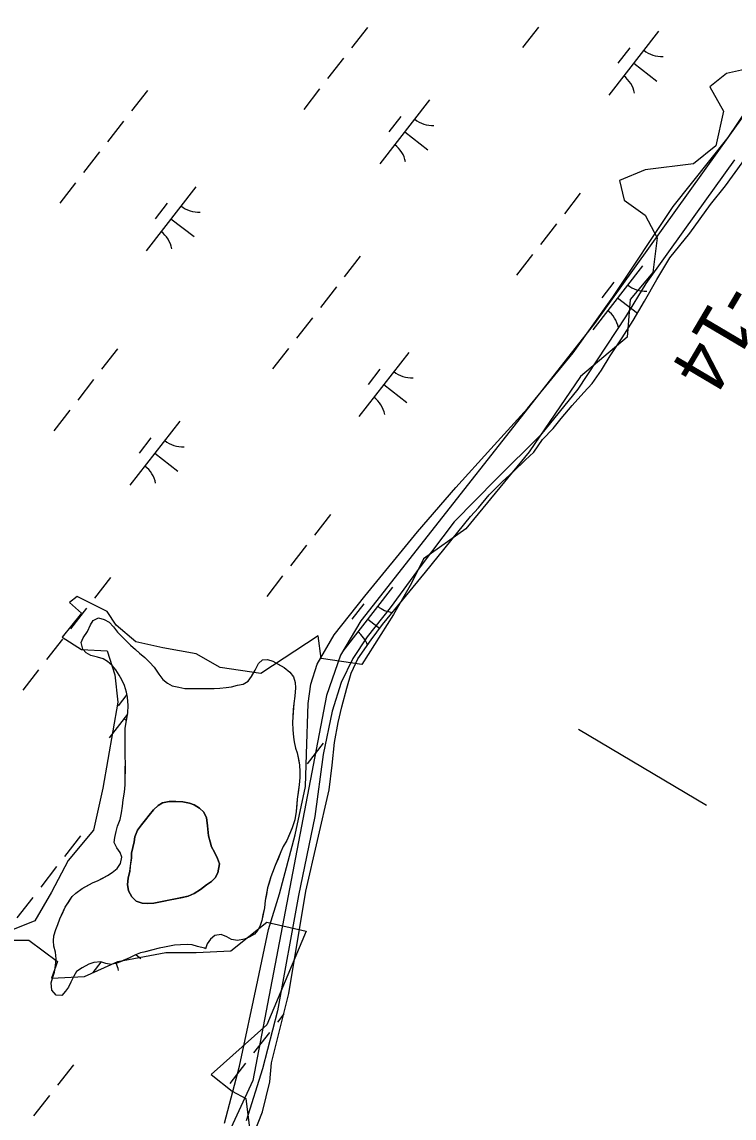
# Model space of a CAD drawing. Extents: x 3888273 to 3909528, y 158682 to 181032.
# Drawn here: x 3897016 to 3897455, y 166620 to 167296 of the extents above; entities that cross this region are included whole.
import ezdxf

# ---------------------------------------------------------------- set-up
doc = ezdxf.new("R2010")
doc.units = 0
for name, color, linetype in [('V-LEVE-TOET', 7, 'Continuous'), ('V-RIVR-EDGE', 7, 'Continuous'), ('V-RIVR-JETY', 7, 'Continuous'), ('V-RIVR-RANG', 7, 'Continuous'), ('V-RRAP-FSHR', 7, 'Continuous'), ('V-TOPO-SHOR', 7, 'Continuous'), ('V-WETL-SWMP', 7, 'Continuous')]:
    doc.layers.add(name, color=color, linetype=linetype)

msp = doc.modelspace()

# ---------------------------------------------------------------- linework, layer by layer
at = {"layer": 'V-LEVE-TOET'}
msp.add_line((3897359.17, 166859.83), (3897438.06, 166813.05), dxfattribs=at)
at = {"layer": 'V-RIVR-EDGE'}
for points in [[(3897463.44, 167266.8), (3897450.43, 167264.01), (3897440.21, 167255.65), (3897448.57, 167240.78), (3897443.93, 167219.41), (3897429.99, 167208.26), (3897400.25, 167204.54), (3897384.46, 167198.04), (3897387.25, 167185.96), (3897400.25, 167176.67), (3897407.69, 167162.73), (3897404.9, 167141.36), (3897390.96, 167124.63), (3897389.1, 167101.4), (3897360.3, 167077.24), (3897328.71, 167030.78), (3897289.68, 166983.39), (3897263.66, 166964.81), (3897256.23, 166949.94), (3897245.08, 166930.43), (3897225.56, 166899.76), (3897200.47, 166903.48), (3897198.62, 166917.42), (3897163.31, 166894.19), (3897138.22, 166897.9), (3897123.35, 166906.27), (3897102.91, 166909.98), (3897086.18, 166913.7), (3897074.1, 166923.92), (3897068.53, 166932.28), (3897049.94, 166941.58), (3897045.3, 166937.86), (3897052.73, 166931.35), (3897040.65, 166916.49), (3897052.73, 166909.05), (3897068.53, 166908.12), (3897073.17, 166893.26), (3897075.03, 166876.53), (3897065.74, 166823.57), (3897060.16, 166797.55), (3897044.37, 166778.96), (3897034.15, 166759.45), (3897023.92, 166741.8), (3896991.4, 166728.79)], [(3897006.27, 166729.72), (3897020.21, 166729.72), (3897037.86, 166716.71), (3897034.15, 166706.49), (3897054.59, 166707.41), (3897075.03, 166716.71), (3897104.77, 166722.28), (3897123.35, 166722.28), (3897144.72, 166723.21), (3897167.02, 166740.87), (3897191.18, 166735.29), (3897167.02, 166677.68), (3897132.64, 166647.02), (3897145.65, 166636.8), (3897154.01, 166632.15), (3897157.73, 166602.41)]]:
    msp.add_lwpolyline(points, dxfattribs=at)
at = {"layer": 'V-RIVR-JETY'}
for points in [[(3897140.87, 166617.01), (3897150.12, 166652.22), (3897161.46, 166705.07), (3897167.94, 166736.38), (3897174.75, 166758.28), (3897184.41, 166794.67), (3897190.89, 166824.42), (3897191.41, 166844.41), (3897192.41, 166875.76), (3897194.06, 166887.51), (3897198.06, 166900.02), (3897208.38, 166917.98), (3897227.35, 166941.76), (3897259.77, 166981.53), (3897283.47, 167008.8), (3897305.19, 167032.57), (3897327.7, 167057.5), (3897355.77, 167091.8), (3897380.3, 167126.13), (3897417.53, 167181.93), (3897451.53, 167224.43), (3897481.62, 167269.3)], [(3897455.35, 167210.68), (3897424.49, 167167.77), (3897400.74, 167134.62), (3897388.06, 167113.93), (3897358.75, 167069.44), (3897335.82, 167040.98), (3897308.59, 167014.12), (3897282.54, 166987.64), (3897261.58, 166959.96), (3897242.98, 166934.6), (3897228.75, 166916.67), (3897220.04, 166903.4), (3897212.88, 166888.55), (3897207.27, 166870.95), (3897201.6, 166844.34), (3897196.64, 166805.96), (3897186.51, 166757.42), (3897173.48, 166686.17), (3897164.22, 166650.56), (3897154.21, 166618.49)]]:
    msp.add_lwpolyline(points, dxfattribs=at)
at = {"layer": 'V-RRAP-FSHR'}
msp.add_lwpolyline([(3898196.37, 168382.23), (3898103.96, 168220.1), (3898005.26, 168066.32), (3897954.7, 167980.85), (3897782.09, 167712.12), (3897715.06, 167605.2), (3897594.98, 167427.26), (3897494.39, 167284.8), (3897369.09, 167109.94), (3897224.96, 166926.54), (3897212.35, 166905.51), (3897203.65, 166880.65), (3897158.27, 166643.31), (3897140.99, 166606.01)], dxfattribs=at)
at = {"layer": 'V-TOPO-SHOR'}
for points in [[(3897091.08, 166722.46), (3897089.03, 166721.94), (3897086.02, 166720.71), (3897082.27, 166718.87), (3897077.64, 166716.9), (3897074.51, 166715.68), (3897071.01, 166714.83), (3897067.64, 166715.35), (3897064.53, 166716.37), (3897060.28, 166716.15), (3897057.16, 166714.92), (3897053.02, 166712.83), (3897049.51, 166710.48), (3897047.87, 166707.62), (3897045.98, 166704.01), (3897044.71, 166700.9), (3897042.82, 166698.3), (3897040.43, 166695.69), (3897037.06, 166695.96), (3897034.34, 166698.98), (3897033.87, 166703.47), (3897034.89, 166707.08), (3897035.91, 166710.07), (3897036.69, 166714.19), (3897037.09, 166718.3), (3897036.62, 166722.42), (3897035.64, 166726.17), (3897035.29, 166729.42), (3897035.69, 166732.41), (3897036.84, 166736.4), (3897038.1, 166739.39), (3897039.38, 166743), (3897041.4, 166747.35), (3897042.67, 166750.21), (3897044.81, 166753.44), (3897046.96, 166756.67), (3897049.22, 166758.78), (3897052.98, 166761.62), (3897055.73, 166763.1), (3897059.37, 166765.07), (3897062.87, 166766.55), (3897065.75, 166768.02), (3897068.64, 166769.63), (3897071.64, 166771.6), (3897074.66, 166774.08), (3897076.8, 166777.06), (3897077.45, 166780.92), (3897076.47, 166783.93), (3897074.37, 166786.81), (3897072.89, 166790.07), (3897073.16, 166793.06), (3897073.94, 166796.8), (3897074.83, 166800.16), (3897076.48, 166804.14), (3897077.39, 166808.38), (3897078.04, 166812.49), (3897078.44, 166816.36), (3897079.22, 166821.09), (3897079.62, 166825.58), (3897079.66, 166830.45), (3897079.69, 166835.44), (3897079.71, 166838.81), (3897079.49, 166842.93), (3897079.52, 166847.18), (3897079.54, 166850.92), (3897079.58, 166855.91), (3897079.61, 166860.53), (3897080.39, 166865.14), (3897081.17, 166869.88), (3897081.45, 166874.37), (3897080.99, 166879.49), (3897080.39, 166882.73), (3897079.17, 166886.74), (3897077.57, 166890.24), (3897075.96, 166893.12), (3897073.86, 166896.51), (3897071.51, 166899.02), (3897068.66, 166901.66), (3897066.05, 166903.17), (3897062.44, 166904.32), (3897058.32, 166905.22), (3897055.59, 166906.99), (3897053.49, 166909.25), (3897052.52, 166913.25), (3897053.66, 166916.24), (3897056.31, 166920.09), (3897058.2, 166924.07), (3897059.85, 166926.93), (3897063.23, 166928.4), (3897066.71, 166927.5), (3897069.7, 166925.74), (3897072.3, 166922.85), (3897074.9, 166919.71), (3897077.13, 166917.32), (3897079.85, 166914.81), (3897082.95, 166911.67), (3897085.93, 166909.03), (3897088.41, 166906.77), (3897091.64, 166904.12), (3897094.61, 166901.23), (3897097.46, 166897.97)], [(3897097.46, 166897.97), (3897100.3, 166893.83), (3897102.9, 166890.44), (3897105.63, 166888.18), (3897108.49, 166886.66), (3897112.6, 166885.64), (3897116.34, 166884.99), (3897122.08, 166884.95), (3897125.33, 166884.92), (3897130.07, 166884.89), (3897134.56, 166884.86), (3897137.93, 166885.21), (3897141.93, 166885.44), (3897145.18, 166886.04), (3897148.93, 166886.89), (3897152.43, 166887.49), (3897155.43, 166889.46), (3897157.57, 166892.32), (3897159.85, 166896.3), (3897161.75, 166900.4), (3897164.26, 166902.51), (3897167.38, 166902.74), (3897170.62, 166901.84), (3897173.48, 166900.2), (3897177.58, 166897.8), (3897181.18, 166894.9), (3897183.41, 166892.14), (3897184.5, 166888.52), (3897184.61, 166885.27), (3897184.2, 166880.16), (3897183.54, 166875.67), (3897183.27, 166871.93), (3897182.99, 166867.56), (3897182.84, 166863.94), (3897182.93, 166859.45), (3897183.4, 166854.95), (3897183.88, 166851.96), (3897184.73, 166848.21), (3897185.58, 166845.33), (3897186.43, 166841.33), (3897187.03, 166837.96), (3897187.25, 166833.46), (3897187.23, 166830.1), (3897186.95, 166825.6), (3897186.29, 166820.87), (3897185.76, 166816.62), (3897185.49, 166813.38), (3897185.08, 166809.02), (3897184.18, 166804.03), (3897182.65, 166799.05), (3897181.13, 166795.57), (3897179.35, 166791.34), (3897177.08, 166787.48), (3897175.56, 166784.25), (3897173.91, 166780.02), (3897172.13, 166775.79), (3897170.86, 166772.55), (3897169.46, 166768.82), (3897168.31, 166765.08), (3897167.42, 166762.09), (3897166.65, 166757.98), (3897165.87, 166754.24), (3897165.46, 166749.75), (3897164.56, 166745.39), (3897163.79, 166741.9), (3897162.77, 166738.79), (3897161.38, 166736.05), (3897159.36, 166733.57), (3897155.98, 166731.59), (3897153.23, 166730.37), (3897148.85, 166729.52), (3897145.11, 166730.17), (3897142.25, 166731.81), (3897138.77, 166733.33), (3897134.9, 166732.61), (3897132.26, 166730.51), (3897130.25, 166727.65), (3897129.23, 166724.41), (3897128.48, 166724.92)], [(3897137.82, 166776.89), (3897136.47, 166780.15), (3897134.62, 166784.15), (3897132.9, 166787.41), (3897131.92, 166790.41), (3897131.07, 166794.04), (3897130.6, 166798.53), (3897130.25, 166802.03), (3897129.65, 166805.28), (3897128.05, 166808.66), (3897125.45, 166811.17), (3897122.22, 166813.19), (3897119.23, 166814.33), (3897115.12, 166815.11), (3897110.88, 166815.26), (3897106.63, 166815.29), (3897102.51, 166814.45), (3897099.88, 166812.84), (3897097.11, 166810.12), (3897094.35, 166806.89), (3897092.2, 166804.03), (3897089.56, 166800.81), (3897087.17, 166797.58), (3897085.52, 166793.6), (3897085.12, 166790.48), (3897084.23, 166786.87), (3897083.58, 166783.5), (3897083.43, 166780.26), (3897082.77, 166775.52), (3897082.38, 166772.4), (3897081.48, 166768.04), (3897080.95, 166764.18), (3897081.55, 166760.18), (3897083.65, 166756.42), (3897086.37, 166753.91), (3897090.11, 166752.63), (3897093.35, 166752.36), (3897097.22, 166752.58), (3897100.35, 166753.31), (3897103.35, 166753.79), (3897106.34, 166754.39), (3897110.59, 166755.24), (3897114.97, 166756.21), (3897118.34, 166756.93), (3897122.22, 166758.53), (3897125.98, 166761), (3897129.75, 166763.97), (3897132.75, 166765.95), (3897135.02, 166768.3), (3897136.79, 166771.41), (3897137.82, 166776.89)], [(3897128.48, 166724.92), (3897124.12, 166725.82), (3897120.88, 166726.84), (3897117.76, 166727.11), (3897113.77, 166727.01), (3897110.02, 166726.67), (3897106.9, 166726.19), (3897103.78, 166725.59), (3897100.53, 166724.86), (3897095.9, 166723.64), (3897092.9, 166722.91), (3897091.08, 166722.46)]]:
    msp.add_lwpolyline(points, dxfattribs=at)
at = {"layer": 'V-WETL-SWMP'}
for p, q in [((3897228.99, 167292.35), (3897219.16, 167279.72)), ((3897334.45, 167292.59), (3897324.63, 167279.96)), ((3897408.59, 167290.12), (3897377.89, 167250.65)), ((3897390.84, 167279.86), (3897383.47, 167270.39)), ((3897214.25, 167273.41), (3897204.42, 167260.78)), ((3897393.24, 167270.39), (3897407.45, 167259.33)), ((3897199.51, 167254.46), (3897189.69, 167241.84)), ((3897093.28, 167253.5), (3897083.45, 167240.87)), ((3897267.35, 167247.67), (3897236.65, 167208.21)), ((3897449.78, 167194.71), (3897486.56, 167245.62)), ((3897078.54, 167234.55), (3897068.71, 167221.93)), ((3897249.6, 167237.41), (3897242.23, 167227.94)), ((3897252, 167227.94), (3897266.21, 167216.88)), ((3897063.8, 167215.61), (3897053.98, 167202.98)), ((3897049.06, 167196.67), (3897039.24, 167184.04)), ((3897123.21, 167194.2), (3897092.5, 167154.74)), ((3897440.47, 167183.29), (3897449.78, 167194.71)), ((3897360.27, 167190.2), (3897350.44, 167177.57)), ((3897105.45, 167183.94), (3897098.08, 167174.47)), ((3897427.87, 167165.65), (3897440.47, 167183.29)), ((3897107.85, 167174.47), (3897122.06, 167163.41)), ((3897345.53, 167171.26), (3897335.7, 167158.63)), ((3897415.53, 167150.26), (3897427.87, 167165.65)), ((3897224.56, 167151.35), (3897214.73, 167138.72)), ((3897330.79, 167152.32), (3897320.97, 167139.69)), ((3897407.46, 167137.09), (3897415.53, 167150.26)), ((3897398.63, 167145.52), (3897367.93, 167106.06)), ((3897380.88, 167135.27), (3897373.51, 167125.79)), ((3897399.88, 167123.66), (3897407.46, 167137.09)), ((3897209.82, 167132.41), (3897199.99, 167119.78)), ((3897383.28, 167125.79), (3897395.5, 167116.28)), ((3897392.81, 167111.73), (3897399.88, 167123.66)), ((3897195.08, 167113.47), (3897185.26, 167100.84)), ((3897386, 167101.05), (3897392.81, 167111.73)), ((3897378.68, 167089.86), (3897386, 167101.05)), ((3897074.88, 167094.28), (3897065.06, 167081.66)), ((3897180.34, 167094.53), (3897170.52, 167081.9)), ((3897254.49, 167092.05), (3897223.78, 167052.59)), ((3897373.38, 167081.17), (3897378.68, 167089.86)), ((3897236.73, 167081.8), (3897229.36, 167072.32)), ((3897367.58, 167072.97), (3897373.38, 167081.17)), ((3897060.14, 167075.34), (3897050.32, 167062.71)), ((3897239.14, 167072.32), (3897253.34, 167061.27)), ((3897362.55, 167067.26), (3897367.58, 167072.97)), ((3897355.26, 167059.32), (3897362.55, 167067.26)), ((3897348.47, 167051.38), (3897355.26, 167059.32)), ((3897045.41, 167056.4), (3897035.58, 167043.77)), ((3897113.25, 167049.6), (3897082.54, 167010.14)), ((3897336.9, 167038.48), (3897343.44, 167045.18)), ((3897343.44, 167045.18), (3897348.47, 167051.38)), ((3897095.49, 167039.35), (3897088.12, 167029.88)), ((3897331.6, 167030.53), (3897336.9, 167038.48)), ((3897097.89, 167029.87), (3897112.1, 167018.82)), ((3897319.04, 167018.64), (3897326.33, 167025.58)), ((3897326.33, 167025.58), (3897331.6, 167030.53)), ((3897312.01, 167012.2), (3897319.04, 167018.64)), ((3897303.97, 167004.26), (3897312.01, 167012.2)), ((3897297.43, 166996.32), (3897303.97, 167004.26)), ((3897206.16, 166992.14), (3897196.34, 166979.51)), ((3897264.71, 166956.61), (3897292.65, 166990.86)), ((3897292.65, 166990.86), (3897297.43, 166996.32)), ((3897191.42, 166973.2), (3897181.6, 166960.57)), ((3897070.45, 166953.29), (3897060.63, 166940.66)), ((3897176.69, 166954.26), (3897166.86, 166941.63)), ((3897238.29, 166924.34), (3897264.71, 166956.61)), ((3897244.53, 166947.46), (3897213.82, 166908)), ((3897226.77, 166937.2), (3897219.4, 166927.73)), ((3897055.71, 166934.35), (3897045.89, 166921.72)), ((3897056.31, 166920.09), (3897058.2, 166924.07)), ((3897058.2, 166924.07), (3897059.85, 166926.93)), ((3897059.85, 166926.93), (3897063.23, 166928.4)), ((3897063.23, 166928.4), (3897066.71, 166927.51)), ((3897066.71, 166927.51), (3897069.7, 166925.74)), ((3897069.7, 166925.74), (3897072.3, 166922.85)), ((3897229.17, 166927.73), (3897236.54, 166922)), ((3897231.23, 166914.91), (3897238.29, 166924.34)), ((3897053.66, 166916.24), (3897056.31, 166920.09)), ((3897072.3, 166922.85), (3897074.9, 166919.71)), ((3897074.9, 166919.71), (3897077.13, 166917.32)), ((3897077.13, 166917.32), (3897079.85, 166914.81)), ((3897040.98, 166915.4), (3897031.15, 166902.78)), ((3897052.52, 166913.25), (3897053.66, 166916.24)), ((3897053.49, 166909.25), (3897052.52, 166913.25)), ((3897079.85, 166914.81), (3897082.95, 166911.67)), ((3897082.95, 166911.67), (3897088.41, 166906.77)), ((3897223.17, 166903.23), (3897231.23, 166914.91)), ((3897055.59, 166906.99), (3897053.49, 166909.25)), ((3897058.33, 166905.22), (3897055.59, 166906.99)), ((3897062.44, 166904.32), (3897058.33, 166905.22)), ((3897066.05, 166903.17), (3897062.44, 166904.32)), ((3897068.66, 166901.66), (3897066.05, 166903.17)), ((3897088.41, 166906.77), (3897091.64, 166904.12)), ((3897091.64, 166904.12), (3897094.61, 166901.23)), ((3897218.86, 166894.28), (3897223.17, 166903.23)), ((3897026.24, 166896.46), (3897016.41, 166883.83)), ((3897071.51, 166899.02), (3897068.66, 166901.66)), ((3897073.87, 166896.51), (3897071.51, 166899.02)), ((3897075.96, 166893.12), (3897073.87, 166896.51)), ((3897094.61, 166901.23), (3897097.46, 166897.97)), ((3897097.46, 166897.97), (3897100.3, 166893.83)), ((3897157.57, 166892.32), (3897159.85, 166896.3)), ((3897159.85, 166896.3), (3897161.75, 166900.4)), ((3897161.75, 166900.4), (3897164.26, 166902.51)), ((3897164.26, 166902.51), (3897167.38, 166902.73)), ((3897167.38, 166902.73), (3897170.62, 166901.84)), ((3897170.62, 166901.84), (3897177.58, 166897.8)), ((3897177.58, 166897.8), (3897181.18, 166894.9)), ((3897077.57, 166890.24), (3897075.96, 166893.12)), ((3897079.17, 166886.74), (3897077.57, 166890.24)), ((3897100.38, 166893.99), (3897100.28, 166893.86)), ((3897100.3, 166893.83), (3897102.9, 166890.44)), ((3897102.9, 166890.44), (3897105.63, 166888.18)), ((3897155.43, 166889.46), (3897157.57, 166892.32)), ((3897181.18, 166894.9), (3897183.41, 166892.14)), ((3897183.41, 166892.14), (3897184.5, 166888.52)), ((3897216.31, 166885.06), (3897218.86, 166894.28)), ((3897080.39, 166882.73), (3897079.17, 166886.74)), ((3897080.99, 166879.49), (3897080.39, 166882.73)), ((3897105.63, 166888.18), (3897108.49, 166886.66)), ((3897108.49, 166886.66), (3897112.6, 166885.64)), ((3897112.6, 166885.64), (3897116.34, 166884.99)), ((3897116.34, 166884.99), (3897134.56, 166884.86)), ((3897134.56, 166884.86), (3897137.93, 166885.21)), ((3897137.93, 166885.21), (3897141.93, 166885.44)), ((3897141.93, 166885.44), (3897145.18, 166886.04)), ((3897145.18, 166886.04), (3897148.93, 166886.89)), ((3897148.93, 166886.89), (3897152.43, 166887.49)), ((3897152.43, 166887.49), (3897155.43, 166889.46)), ((3897184.61, 166885.27), (3897184.2, 166880.16)), ((3897184.5, 166888.52), (3897184.61, 166885.27)), ((3897213.23, 166873.6), (3897216.31, 166885.06)), ((3897080.67, 166881.22), (3897075.26, 166874.26)), ((3897081.45, 166874.37), (3897080.99, 166879.49)), ((3897184.2, 166880.16), (3897183.54, 166875.67)), ((3897079.61, 166860.53), (3897081.17, 166869.88)), ((3897081.17, 166869.88), (3897081.45, 166874.37)), ((3897183.54, 166875.67), (3897182.99, 166867.56)), ((3897210.92, 166863.88), (3897213.23, 166873.6)), ((3897081.05, 166869.14), (3897069.68, 166854.53)), ((3897182.99, 166867.56), (3897182.84, 166863.94)), ((3897182.84, 166863.94), (3897182.93, 166859.45)), ((3897208.59, 166851.67), (3897210.92, 166863.88)), ((3897079.49, 166842.93), (3897079.61, 166860.53)), ((3897182.93, 166859.45), (3897183.4, 166854.95)), ((3897183.4, 166854.95), (3897183.88, 166851.96)), ((3897183.88, 166851.96), (3897184.73, 166848.21)), ((3897201.73, 166851.14), (3897191.91, 166838.52)), ((3897207.25, 166837.7), (3897208.59, 166851.67)), ((3897079.71, 166838.81), (3897079.49, 166842.93)), ((3897184.73, 166848.21), (3897185.58, 166845.33)), ((3897185.58, 166845.33), (3897187.03, 166837.96)), ((3897079.62, 166825.58), (3897079.71, 166838.81)), ((3897187.03, 166837.96), (3897187.25, 166833.46)), ((3897205.4, 166822.49), (3897207.25, 166837.7)), ((3897187.23, 166830.09), (3897186.95, 166825.6)), ((3897187.25, 166833.46), (3897187.23, 166830.09)), ((3897079.22, 166821.1), (3897079.62, 166825.58)), ((3897186.95, 166825.6), (3897185.76, 166816.63)), ((3897190.99, 166759.94), (3897205.4, 166822.49)), ((3897078.04, 166812.49), (3897078.44, 166816.36)), ((3897078.44, 166816.36), (3897079.22, 166821.1)), ((3897185.76, 166816.63), (3897185.09, 166809.02)), ((3897077.38, 166808.38), (3897078.04, 166812.49)), ((3897185.09, 166809.02), (3897184.18, 166804.03)), ((3897074.83, 166800.16), (3897076.48, 166804.14)), ((3897076.48, 166804.14), (3897077.38, 166808.38)), ((3897184.18, 166804.03), (3897182.65, 166799.05)), ((3897073.16, 166793.06), (3897073.94, 166796.8)), ((3897073.94, 166796.8), (3897074.83, 166800.16)), ((3897182.65, 166799.05), (3897179.35, 166791.34)), ((3897052.06, 166794.08), (3897042.23, 166781.45)), ((3897072.89, 166790.06), (3897073.16, 166793.06)), ((3897074.37, 166786.81), (3897072.89, 166790.06)), ((3897179.35, 166791.34), (3897177.08, 166787.48)), ((3897076.47, 166783.93), (3897074.37, 166786.81)), ((3897077.45, 166780.92), (3897076.47, 166783.93)), ((3897175.56, 166784.25), (3897172.13, 166775.79)), ((3897177.08, 166787.48), (3897175.56, 166784.25)), ((3897037.32, 166775.13), (3897027.49, 166762.51)), ((3897074.66, 166774.08), (3897076.8, 166777.06)), ((3897076.8, 166777.06), (3897077.45, 166780.92)), ((3897172.13, 166775.79), (3897169.46, 166768.82)), ((3897062.87, 166766.55), (3897068.64, 166769.63)), ((3897068.64, 166769.63), (3897071.64, 166771.6)), ((3897071.64, 166771.6), (3897074.66, 166774.08)), ((3897169.46, 166768.82), (3897167.42, 166762.09)), ((3897049.22, 166758.78), (3897052.98, 166761.62)), ((3897052.98, 166761.62), (3897059.37, 166765.07)), ((3897059.37, 166765.07), (3897062.87, 166766.55)), ((3897167.42, 166762.09), (3897165.87, 166754.24)), ((3897022.58, 166756.19), (3897012.75, 166743.56)), ((3897042.67, 166750.21), (3897046.96, 166756.67)), ((3897046.96, 166756.67), (3897049.22, 166758.78)), ((3897180.58, 166696.86), (3897190.99, 166759.94)), ((3897039.38, 166742.99), (3897042.67, 166750.21)), ((3897165.46, 166749.75), (3897163.79, 166741.9)), ((3897165.87, 166754.24), (3897165.46, 166749.75)), ((3897038.1, 166739.38), (3897039.38, 166742.99)), ((3897163.79, 166741.9), (3897162.77, 166738.79)), ((3897035.69, 166732.41), (3897036.84, 166736.4)), ((3897036.84, 166736.4), (3897038.1, 166739.38)), ((3897161.38, 166736.05), (3897159.37, 166733.57)), ((3897162.77, 166738.79), (3897161.38, 166736.05)), ((3897035.29, 166729.42), (3897035.69, 166732.41)), ((3897035.64, 166726.17), (3897035.29, 166729.42)), ((3897130.25, 166727.65), (3897129.23, 166724.41)), ((3897132.26, 166730.51), (3897130.25, 166727.65)), ((3897134.9, 166732.61), (3897132.26, 166730.51)), ((3897138.77, 166733.33), (3897134.9, 166732.61)), ((3897142.26, 166731.81), (3897138.77, 166733.33)), ((3897145.12, 166730.17), (3897142.26, 166731.81)), ((3897148.85, 166729.52), (3897145.12, 166730.17)), ((3897153.23, 166730.36), (3897148.85, 166729.52)), ((3897155.98, 166731.59), (3897153.23, 166730.36)), ((3897159.37, 166733.57), (3897155.98, 166731.59)), ((3897036.62, 166722.42), (3897035.64, 166726.17)), ((3897037.09, 166718.3), (3897036.62, 166722.42)), ((3897086.02, 166720.71), (3897082.27, 166718.87)), ((3897089.03, 166721.94), (3897086.02, 166720.71)), ((3897086.38, 166720.86), (3897089.27, 166718.61)), ((3897091.08, 166722.46), (3897089.03, 166721.94)), ((3897100.53, 166724.86), (3897091.08, 166722.46)), ((3897103.78, 166725.58), (3897100.53, 166724.86)), ((3897110.02, 166726.67), (3897103.78, 166725.58)), ((3897113.77, 166727.01), (3897110.02, 166726.67)), ((3897117.76, 166727.11), (3897113.77, 166727.01)), ((3897120.88, 166726.84), (3897117.76, 166727.11)), ((3897124.12, 166725.82), (3897120.88, 166726.84)), ((3897128.48, 166724.92), (3897124.12, 166725.82)), ((3897129.23, 166724.41), (3897128.48, 166724.92)), ((3897035.91, 166710.07), (3897036.69, 166714.19)), ((3897036.69, 166714.19), (3897037.09, 166718.3)), ((3897057.16, 166714.92), (3897053.02, 166712.83)), ((3897060.28, 166716.15), (3897057.16, 166714.92)), ((3897064.68, 166716.32), (3897059.72, 166709.93)), ((3897064.53, 166716.37), (3897060.28, 166716.15)), ((3897067.64, 166715.35), (3897064.53, 166716.37)), ((3897071.01, 166714.83), (3897067.64, 166715.35)), ((3897074.51, 166715.68), (3897071.01, 166714.83)), ((3897082.27, 166718.87), (3897074.51, 166715.68)), ((3897033.87, 166703.47), (3897034.89, 166707.08)), ((3897034.89, 166707.08), (3897035.91, 166710.07)), ((3897047.87, 166707.62), (3897045.98, 166704.01)), ((3897049.51, 166710.48), (3897047.87, 166707.62)), ((3897053.02, 166712.83), (3897049.51, 166710.48)), ((3897034.33, 166698.98), (3897033.87, 166703.47)), ((3897044.71, 166700.9), (3897042.82, 166698.29)), ((3897045.98, 166704.01), (3897044.71, 166700.9)), ((3897037.06, 166695.96), (3897034.33, 166698.98)), ((3897040.43, 166695.69), (3897037.06, 166695.96)), ((3897042.82, 166698.29), (3897040.43, 166695.69)), ((3897169.81, 166654.26), (3897180.58, 166696.86)), ((3897177.41, 166684.31), (3897173.51, 166679.3)), ((3897168.6, 166672.99), (3897158.77, 166660.36)), ((3897047.63, 166653.08), (3897037.8, 166640.45)), ((3897153.86, 166654.05), (3897144.04, 166641.42)), ((3897168.73, 166642.53), (3897169.81, 166654.26)), ((3897164.36, 166624.09), (3897168.73, 166642.53)), ((3897032.89, 166634.14), (3897023.06, 166621.51)), ((3897159.03, 166610.4), (3897164.36, 166624.09))]:
    msp.add_line(p, q, dxfattribs=at)
msp.add_lwpolyline([(3897137.82, 166776.89), (3897136.79, 166771.41), (3897135.02, 166768.3), (3897132.75, 166765.95), (3897129.75, 166763.97), (3897125.98, 166761), (3897122.22, 166758.53), (3897118.34, 166756.93), (3897110.59, 166755.24), (3897103.35, 166753.79), (3897100.35, 166753.31), (3897097.22, 166752.58), (3897093.35, 166752.36), (3897090.11, 166752.63), (3897086.37, 166753.91), (3897083.65, 166756.42), (3897081.55, 166760.18), (3897080.95, 166764.18), (3897081.48, 166768.04), (3897082.38, 166772.4), (3897083.43, 166780.26), (3897083.58, 166783.5), (3897084.23, 166786.87), (3897085.12, 166790.48), (3897085.52, 166793.6), (3897087.17, 166797.58), (3897089.56, 166800.81), (3897092.21, 166804.03), (3897094.35, 166806.89), (3897097.11, 166810.12), (3897099.88, 166812.84), (3897102.51, 166814.45), (3897106.63, 166815.29), (3897110.88, 166815.26), (3897115.12, 166815.11), (3897119.23, 166814.33), (3897122.22, 166813.19), (3897125.45, 166811.17), (3897128.05, 166808.66), (3897129.65, 166805.28), (3897130.25, 166802.03), (3897131.07, 166794.04), (3897131.92, 166790.41), (3897132.9, 166787.41), (3897134.62, 166784.15), (3897136.47, 166780.15)], close=True, dxfattribs=at)
for centre, start, end in [((3897410.39, 167292.04), 231.34298, 272.88664), ((3897376.47, 167248.44), 11.34298, 52.88663), ((3897269.15, 167249.59), 231.34298, 272.88664), ((3897235.23, 167205.99), 11.34298, 52.88663), ((3897125, 167196.12), 231.34298, 272.88664), ((3897091.08, 167152.52), 11.34298, 52.88663), ((3897400.43, 167147.45), 231.34298, 272.88664), ((3897366.51, 167103.85), 11.34298, 52.88663), ((3897256.28, 167093.98), 231.34298, 272.88664), ((3897222.36, 167050.38), 11.34298, 52.88663), ((3897115.04, 167051.53), 231.34298, 272.88664), ((3897081.12, 167007.93), 11.34298, 52.88663), ((3897246.32, 166949.38), 231.34298, 263.86924), ((3897212.4, 166905.78), 19.56463, 52.88663), ((3897068.25, 166852.31), 46.54491, 52.88663), ((3897058.29, 166707.72), 11.34298, 26.45297)]:
    msp.add_arc(centre, 17.62, start, end, dxfattribs=at)

# ---------------------------------------------------------------- texts
at = {"layer": 'V-RIVR-RANG'}
msp.add_text('-14', height=33.5, rotation=239.41833, dxfattribs=at).set_placement((3897448.13, 167137.14))

doc.saveas('drawing.dxf')
